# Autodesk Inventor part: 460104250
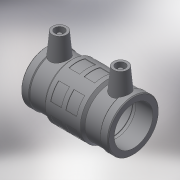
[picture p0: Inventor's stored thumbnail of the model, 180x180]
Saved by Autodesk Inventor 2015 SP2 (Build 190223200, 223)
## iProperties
Created: 2017-06
Part Number: 460104250
Material: Generic
Description: PLASSON LIGHTFIT COUPLER 250
Document SubType Name: Modeling
Designer: KIM
Mass: 89.5427 g
Surface Area: 304.58 cm^2
Volume: 89.5427 cm^3
Density: 1 g/cm^3
Appearance: Default
Author: KIM
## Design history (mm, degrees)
derived "460104.ipt"
feature "Solid1::460104.ipt"
tag "TaggingFeature1"
body "Solid1"
other parameters: "d13" = 256, "d14" = 17.6296, "d15" = 126, "d16" = 126, "d17" = 247.5, "d19" = 3.52592, "d20" = 168 deg, "d22" = 275.42, "d23" = 293, "d24" = 267.1574, "d25" = 135 deg, "d26" = 102.4, "d27" = 135 deg, "d29" = 155, "d35" = 15, "d39" = 5 deg, "d44" = 4, "d46" = 14, "d47" = 0, "d52" = 287.14, "d53" = 12.8, "d54" = 12.8, "d55" = 12.8, "d56" = 35 deg, "d58" = 360 deg, "d60" = 25.2, "d61" = 135 deg, "d62" = 115.2, "d63" = 3, "d64" = 0, "L_" = 256, "L_1" = 126, "D_" = 293, "A_" = 155, "d_2" = 12
